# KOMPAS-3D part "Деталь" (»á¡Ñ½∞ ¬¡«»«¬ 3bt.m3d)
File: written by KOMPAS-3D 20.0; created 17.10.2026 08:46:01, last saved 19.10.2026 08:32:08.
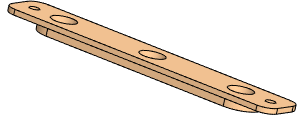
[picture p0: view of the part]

Document properties: Полное имя файла: D:\RicWork\Project-EPS32\box_compas\корпус\панель кнопок.m3d

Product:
- Part/product: Деталь
    Масса: 0.0305378

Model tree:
1. Эскиз:1
2. Элемент выдавливания:1
     Расстояние 1 = 1.6
3. Эскиз:5  (with: Элемент выдавливания:1)
4. Элемент выдавливания:6
     Расстояние 2 = 1.6
5. Эскиз:6  (with: Элемент выдавливания:1, Элемент выдавливания:6)
6. Элемент выдавливания:7
     Расстояние 1 = 2.4
7. Эскиз:7  (with: Элемент выдавливания:7, Элемент выдавливания:1)
8. Элемент выдавливания:8
     Расстояние 2 = 4
9. Массив по сетке:1  (with: Элемент выдавливания:8, Эскиз:7)  (3 pattern instances)
     Шаг 1 = 30; Угол раствора = 90
10. Элемент выдавливания:9  (with: Элемент выдавливания:1)
     Расстояние 1 = 2
11. Элемент выдавливания:10  (with: Элемент выдавливания:1)
     Расстояние 1 = 2
12. Элемент выдавливания:11  (with: Элемент выдавливания:1)
     Расстояние 2 = 0.25
13. Элемент выдавливания:12  (with: Элемент выдавливания:1)
     Расстояние 2 = 0.25
14. Скругление:5  (with: Элемент выдавливания:1, Скругление:4, Элемент выдавливания:11, Элемент выдавливания:9, Скругление:3, Элемент выдавливания:12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)
     Радиус = 0.6
15. Элемент выдавливания:13  (with: Элемент выдавливания:12)
     Расстояние 2 = 0.2
16. Элемент выдавливания:14  (with: Элемент выдавливания:11)
     Расстояние 2 = 0.2
17. Скругление:6  (with: Элемент выдавливания:14, Элемент выдавливания:13)
     Радиус = 4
